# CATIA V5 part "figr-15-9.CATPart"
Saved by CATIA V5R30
Part number: Part1
Bounding box of the stored display mesh (mm): x -50 to 50, y -32.5 to 33.5, z -52 to 1
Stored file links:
  D:\PROJECTS\CATIA V56R 2020\Resources\Parts File\c15_catia_v5_6r2020_prt\figr-15-9.CATPart
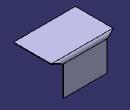
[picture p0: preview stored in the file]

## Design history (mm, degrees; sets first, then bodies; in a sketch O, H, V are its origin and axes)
SheetMetalParameters1: Thickness 1, BendRadius 4, KFactor 0.475772 {= log(min(100,max(20*SheetMetalParameters1.BendRadius,SheetMetalParameters1.Thickness)/SheetMetalParameters1.Thickness))/log(100)/2}, ReliefRadialLength 4, ReliefAxialLength 4, MinimumBendRadius 0
Body1 (main body)
  Sketch1 on xy-plane, origin (0, 0, 0), H (1, 0, 0), V (0, 1, 0)
    line L1 (-50, 32.5) -> (50, 32.5)
    line L2 (50, 32.5) -> (50, -32.5)
    line L3 (50, -32.5) -> (-50, -32.5)
    line L4 (-50, -32.5) -> (-50, 32.5)
    length L1 = 100
    length L2 = 65
    horizontal: L1 H, L3 H
    vertical: L2 V, L4 V
    symmetry: L4 L2 V, L1 L3 H
  Wall1: Thickness 1, Profile Sketch1
  d_NewWallOnEdge1: NewWallOnEdge_Edge edge [face of Wall1 | face of Wall1], NewWallOnEdge_Length 53, NewWallOnEdge_HeightLimitOffset 0, NewWallOnEdge_WidthOffset1 -15, NewWallOnEdge_WidthOffset2 -15, NewWallOnEdge_Angle 90, NewWallOnEdge_BendRadiusValue 4 {= SheetMetalParameters1.BendRadius}, NewWallOnEdge_BendTable SheetMetalParameters1, KFacteur 0.475772 {= log(min(100,max(20*d_NewWallOnEdge1.Radius,SheetMetalParameters1.Thickness)/SheetMetalParameters1.Thickness))/log(100)/2}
